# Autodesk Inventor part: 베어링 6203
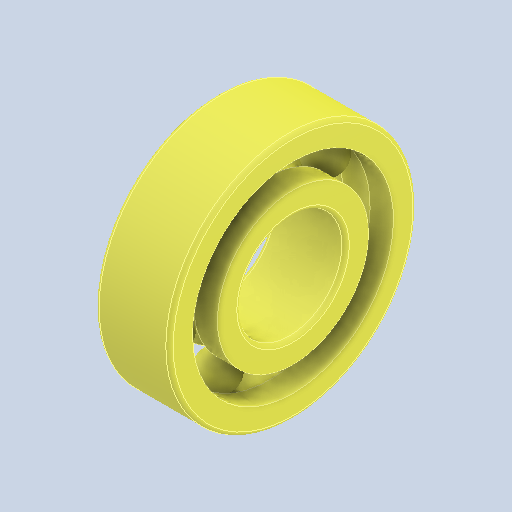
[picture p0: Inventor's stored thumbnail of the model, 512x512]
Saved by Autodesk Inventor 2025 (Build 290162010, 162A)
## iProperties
Created: 2024-07
Part Number: 베어링 6203
Material: 강철, 연강
Description: 깊은 그루브 볼 베어링
Document SubType Name: Modeling
Designer: Admin
Density: 7.86 g/cm^3
Appearance: 기본값
Author: jhkim
Revision Number: 1
Sending System: Autodesk Inventor 2025
Preprocessor: ST-DEVELOPER v20
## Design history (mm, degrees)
feature "Solid1"
feature "Solid1:1"
feature "Solid1:2"
feature "Solid1:3"
feature "Solid1:4"
feature "Solid1:5"
feature "Solid1:6"
feature "Solid1:7"
feature "Solid1:8"
node "솔리드1"
node "솔리드2"
node "솔리드3"
node "솔리드4"
node "솔리드5"
node "솔리드6"
node "솔리드7"
node "솔리드8"
node "솔리드9"
